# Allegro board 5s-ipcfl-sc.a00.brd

Outline 243.84 x 243.84 mm; copper layers: TOP, VCC, IN1, BOTTOM. Coordinates in mm from the lower left corner of the outline.
Outline path: 0,239.78 arc(1.19,242.65) 4.06,243.84 239.78,243.84 arc(242.65,242.65) 243.84,239.78 243.84,4.06 arc(242.65,1.19) 239.78,0 4.06,0 arc(1.19,1.19) 0,4.06 0,239.78

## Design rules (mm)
net group (8/8): nets CLKOUT_LPC1_CLK_R DRAM_RESET#
net group (+19V): nets +12V +12V_CPU
net group ASM1142_RXN: nets ASM1142_RXN ASM1142_RXN_C
net group ASM1142_RXP: nets ASM1142_RXP ASM1142_RXP_C
net group ASM1142_TXN: nets ASM1142_TXN ASM1142_TXN_C
net group ASM1142_TXP: nets ASM1142_TXP ASM1142_TXP_C
net group CEN_B: nets CEN_B CEN_R
net group CFAN_TACH: nets CFAN_TACH SYSFAN_TACH
net group CLKOUT_LPC0: nets CLKOUT_LPC0 CLKOUT_LPC0_ESPI_CLK
net group CPU_VIDSCLK: nets CPU_VIDSCLK VIDSCLK
net group CPU_VIDSOUT: nets CPU_VIDSOUT VIDSOUT
net group DIFFPAIR127: nets CPU_DDI3_AUXN CPU_DDI3_AUXP
net group DP_TXN0_RD_OUT: nets DP_TXN0_RD_OUT ML_LANE_0N
net group DP_TXN1_RD_OUT: nets DP_TXN1_RD_OUT ML_LANE_1N
net group DP_TXN2_RD_OUT: nets DP_TXN2_RD_OUT ML_LANE_2N
net group DP_TXN3_RD_OUT: nets DP_TXN3_RD_OUT ML_LANE_3N
net group DP_TXP0_RD_OUT: nets DP_TXP0_RD_OUT ML_LANE_0P
net group DP_TXP1_RD_OUT: nets DP_TXP1_RD_OUT ML_LANE_1P
net group DP_TXP2_RD_OUT: nets DP_TXP2_RD_OUT ML_LANE_2P
net group DP_TXP3_RD_OUT: nets DP_TXP3_RD_OUT ML_LANE_3P
net group FRAME#_ESPI: nets FRAME#_ESPI LFRAME#_ESPI_CS0#
net group GPP_A6_SERIRQ: nets GPP_A6_SERIRQ SERIRQ_ESPI
net group H_TRST#: nets H_TRST# PCH_H_TRST#
net group LAD0_ESPI_IO0: nets LAD0_ESPI_IO0 LAD_ESPI0
net group LAD0_ESPI_IO1: nets LAD0_ESPI_IO1 LAD_ESPI1
net group LAD0_ESPI_IO2: nets LAD0_ESPI_IO2 LAD_ESPI2
net group LAD0_ESPI_IO3: nets LAD0_ESPI_IO3 LAD_ESPI3
net group LAN_TXN: nets LAN_TXN LAN_TXN_C
net group LAN_TXP: nets LAN_TXP LAN_TXP_C
net group LFE_B: nets LFE_B LFE_R
net group LGHG(20/20): nets +1VSB_HG_D +1VSB_LG_D
net group LINE1_L: nets LINE1_L LINE1_L_B
net group LINE1_R: nets LINE1_R LINE1_R_B
net group LP1+: nets LP1+ USBP1
net group LP1-: nets LP1- USBN1
net group LP2+: nets LP2+ USBP2
net group LP2-: nets LP2- USBN2
net group LP3+: nets LP3+ USBP3
net group LP3-: nets LP3- USBN3
net group LP4+: nets LP4+ USBP4
net group LP4-: nets LP4- USBN4
net group LP5+: nets LP5+ USBP5
net group LP5-: nets LP5- USBN5
net group LP6+: nets LP6+ USBP6
net group LP6-: nets LP6- USBN6
net group LP7+: nets LP7+ USB2_P2_P_CHARGE
net group LP7-: nets LP7- USB2_P2_N_CHARGE
net group LP9+: nets LP9+ USBP9
net group LP9-: nets LP9- USBN9
net group LP10+: nets LP10+ USBP10
net group LP10-: nets LP10- USBN10
net group LP11+: nets LP11+ USBP11
net group LP11-: nets LP11- USBN11
net group LP12+: nets LP12+ USBP12
net group LP12-: nets LP12- USBN12
net group LP13+: nets LP13+ USB2_P1_P_CHARGE
net group LP13-: nets LP13- USB2_P1_N_CHARGE
net group LP14+: nets LP14+ USBP14
net group LP14-: nets LP14- USBN14
net group MIC1_JD: nets MIC1_JD SENSEA
net group MIC2-L: nets MIC2-L XMIC2_L
net group MIC2-R: nets MIC2-R XMIC2_R
net group PCH_SUSACK#: nets PCH_SUSACK# PCH_SUSWARN#
net group PCH_SUSCLK: nets PCH_SUSCLK SSD_SUSCLK
net group PE5_TXN: nets PE5_TXN PE5_TXN_C
net group PE5_TXN1_C: nets PE5_TXN1_C WLAN_TXN1
net group PE5_TXP: nets PE5_TXP PE5_TXP_C
net group PE5_TXP1_C: nets PE5_TXP1_C WLAN_TXP1
net group PE6_TXN: nets PE6_TXN PE6_TXN_C
net group PE6_TXP: nets PE6_TXP PE6_TXP_C
net group PE7_TXN: nets PE7_TXN PE7_TXN_C
net group PE7_TXP: nets PE7_TXP PE7_TXP_C
net group PE8_TXN: nets PE8_TXN PE8_TXN_C
net group PE8_TXP: nets PE8_TXP PE8_TXP_C
net group PE17_TXN: nets PE17_TXN PE17_TXN1_C
net group PE17_TXP: nets PE17_TXP PE17_TXP1_C
net group PE18_TXN: nets PE18_TXN PE18_TXN2_C
net group PE18_TXP: nets PE18_TXP PE18_TXP2_C
net group PE19_TXN: nets PE19_TXN PE19_TXN3_C
net group PE19_TXP: nets PE19_TXP PE19_TXP3_C
net group PE20_TXN: nets PE20_TXN PE20_TXN4_C
net group PE20_TXP: nets PE20_TXP PE20_TXP4_C
net group PROC_AUDIO_CLK: nets PROC_AUDIO_CLK PROC_AUDIO_CLK_R
net group PROC_AUDIO_SDI: nets PROC_AUDIO_SDI PROC_AUDIO_SDI_R
net group PROC_AUDIO_SDO: nets PROC_AUDIO_SDO PROC_AUDIO_SDO_R
net group PS_ON#: nets P1_PSON# PS_ON#
net group SATA_RXN3: nets SATA_RXN3 SATA_RXN3_C
net group SATA_RXP3: nets SATA_RXP3 SATA_RXP3_C
net group SATA_TXN3: nets SATA_TXN3 SATA_TXN3_C
net group SATA_TXP3: nets SATA_TXP3 SATA_TXP3_C
net group SPI_CS0#: nets SPI_CS0# XSPI_CS#
net group U2DM_A: nets U2DM_A U2DM_A-
net group U2DM_B: nets U2DM_B U2DM_B_C
net group U2DP_A: nets U2DP_A U2DP_A+
net group U2DP_B: nets U2DP_B U2DP_B_C
net group U3RXN_A: nets U3RXN_A U3RXN_A_C
net group U3RXP_A: nets U3RXP_A U3RXP_A_C
net group USB3_RX_N1: nets USB3_RX_N1 USB3_RX_N1_C
net group USB3_RX_N2: nets USB3_RX_N2 USB3_RX_N2_C
net group USB3_RX_N3: nets USB3_RX_N3 USB3_RX_N3_C
net group USB3_RX_N4: nets USB3_RX_N4 USB3_RX_N4_C
net group USB3_RX_N5: nets USB3_RX_N5 USB3_RX_N5_C
net group USB3_RX_N6: nets USB3_RX_N6 USB3_RX_N6_C
net group USB3_RX_N7: nets USB3_RX_N7 USB3_RX_N7_C
net group USB3_RX_P1: nets USB3_RX_P1 USB3_RX_P1_C
net group USB3_RX_P2: nets USB3_RX_P2 USB3_RX_P2_C
net group USB3_RX_P3: nets USB3_RX_P3 USB3_RX_P3_C
net group USB3_RX_P4: nets USB3_RX_P4 USB3_RX_P4_C
net group USB3_RX_P5: nets USB3_RX_P5 USB3_RX_P5_C
net group USB3_RX_P6: nets USB3_RX_P6 USB3_RX_P6_C
net group USB3_RX_P7: nets USB3_RX_P7 USB3_RX_P7_C
net group USB3P1_RXN1: nets USB3P1_RXN1 USB3P1_RXN1_C
net group USB3P1_RXN2: nets USB3P1_RXN2 USB3P1_RXN2_C
net group USB3P1_RXP1: nets USB3P1_RXP1 USB3P1_RXP1_C
net group USB3P1_RXP2: nets USB3P1_RXP2 USB3P1_RXP2_C
net group XTAL: nets LAN_XTAL_IN LAN_Y4_25M
net group XTAL_24M_PCH_IN: nets XTAL_24M_PCH_IN Y18_R
net group 50OHM(4|3.5): nets CLKOUT_LPC1 CPU_VIDALERT# DDPD_HPD MF_MODE# SPI_CS# SPI_DI SPI_IO2 SYS_RESET# U4_SPI_CLK U4_SPI_DO
net group 85OHM(DP_4/4/2.5/200): nets LAN_RXN LAN_RXN_C LAN_RXP LAN_RXP_C PCIE_RCOMPN_W15S15MIL PCIE_RCOMPP_W15S15MIL USBN8 USBP8
net group (5/5): nets AZ_BITCLK AZ_RST# AZ_SDATA_OUT AZ_SYNC CPUPWRGD H_TRIGIN H_TRIGOUT H_TRIGOUT_R HDA_AZRST#_L500MIL HDA_BITCLK_24MHZ_L500MIL HDA_SDO_L500MIL HDA_SYNC_L500MIL N23556498 PCH_TGR_L900MIL PCIE-WAKE_C PM_DOWN PM_DOWN_R PM_SYNC PM_SYNC_R PROCHOT# PROCHOT#_R PROCPWRGD SPI_IO2_XDP SPI_MOSI WAKE#
net group (10): nets SIDE-R_C
net group (10/10): nets +BAT_R +BATT CATERR# CEN_JD CENTER CENTER_C FRONT-L FRONT-L_C FRONT-L_MUTE FRONT-R FRONT-R_C FRONT-R_MUTE FRONT_JD FRONT_L FRONT_L_B FRONT_R FRONT_R_B H_THMTRIP# H_THMTRIP#_R JDREF KBRST#_ESPI LAN_WAKE# LANWAKE_N LFE LFE_C LINE1-L LINE1-L_C LINE1-R LINE1-R_C LINE1_JD LINE2-L LINE2-L_C LINE2-L_MUTE LINE2-R LINE2-R_C LINE2-R_MUTE MIC1-L MIC1-L_C MIC1-R MIC1-R_C MIC1-VREFO-L MIC1-VREFO-R MIC1_L_B MIC1_R_B MIC2-L_C MIC2-R_C MIC2-VREFO MUTE PCH_DPWROK PCH_PWROK PLTRST_CPU# RTCRST# S/PDIF_OUT SENSEB SIDE-L SIDE-L_C SIDE-R SIDE_JD SIDESURR_L SIDESURR_L_B SIDESURR_L_MUTE SIDESURR_R SIDESURR_R_B SIDESURR_R_MUTE SRTCRST# SURR-L SURR-L_C SURR-R SURR-R_C SURR_JD SURR_L SURR_L_B SURR_R SURR_R_B XLINE2_L XLINE2_R XMIC2_L_D XMIC2_R_D
net group (15/15): nets EXP_TXN0 EXP_TXN1 EXP_TXN2 EXP_TXN3 EXP_TXN4 EXP_TXN5 EXP_TXN6 EXP_TXN7 EXP_TXP0 EXP_TXP1 EXP_TXP2 EXP_TXP3 EXP_TXP4 EXP_TXP5 EXP_TXP6 EXP_TXP7 PE9_TXN PE9_TXP PE10_TXN PE10_TXP PE11_TXN PE11_TXP PE12_TXN PE12_TXP PECI_PCH PECI_SIO SATA_RXN0 SATA_RXN1 SATA_RXN2 SATA_RXP0 SATA_RXP1 SATA_RXP2 SATA_TXN0 SATA_TXN1 SATA_TXN2 SATA_TXP0 SATA_TXP1 SATA_TXP2 SPI_CLK XSPI_CLK
net group (20/20): nets CK_100M_ASM1142 CK_100M_ASM1142# N23059953 RTCX1_NO_IO_HS_S20MIL XCLK_BIASREF_WSL
net group (25/25): nets RBIAS
net group (PWR_10): nets 3VA_ADJ_A 3VA_ADJ_C_A +1VSB_DUAL_IN_CRT_MAIN +1VSB_DUAL_IN_CRT_MAIN_R +1VSB_DUAL_IN_CRT_SB_R +1VSB_FB_A +1VSB_FB_RC_A +1VSB_TST_A +1VSB_VCC_A +CPUIO_FB_A +CPUIO_FBR_A CC1 CC2 SLP_SUS#_CRT_R VCC_SENSE VCCGT_SENSE VCCIO_SENSE VCCSA_SENSE VGT_COMP_A VGT_FB_A VGT_IMON_A VRM_EN_A VSS_SENSE VSSGT_SENSE
net group (PWR_15): nets +V1P0A_VCCF24_W15MIL CC_VCONN CC_VCONN_EN
net group (PWR_20): nets +0P95V_CPUIO +1P2V +1P2V_DUAL +1P2V_FB +1P2V_FB_R +1P2V_SUS +1P2V_VDD +1P05V_SA +1V_DCPDSW +1V_ST +1VSB +1VSB_BOT_C +1VSB_BOTR_C +1VSB_SN +1VSB_TRIP +1VSB_VIN +2P5V_VPP +3.3V_SUS +3P3V +3P3V_DP +3P3VA +3P3VSB +5V +5V_1VSB_IN +5V_DUAL +5VA +5VSB +12V_GFX +CPUIO_RC1 +CPUIO_RC2 +CPUIO_SS +USB_TYPEC +VCCGT +VCORE +VTT_DDR AGND BAT GND VGT_PWM1_SN VGT_PWM2_BOT_C VGT_PWM2_BOTR_C VGT_PWM2_SN VGT_PWM2_VCC_C VRM_PWM1_SN VRM_PWM2_SN VRM_PWM3_BOT_C VRM_PWM3_BOTR_C VRM_PWM3_SN VRM_PWM3_VCC_C VRM_PWM4_BOT_C VRM_PWM4_BOTR_C VRM_PWM4_SN VRM_PWM4_VCC_C
net group (PWR_25): nets +1VSB_HGR_D +1VSB_SW_C +CPUIO_DRV_D +CPUIO_DRVR_D +V1P0A_VCCAMPHYPLL_W25MIL VGT_PWM1_HGR_D VGT_PWM2_HG_D VGT_PWM2_HGR_D VGT_PWM2_LG_D VGT_PWM2_SW_C VRM_PWM1_HGR_D VRM_PWM2_HGR_D VRM_PWM3_HG_D VRM_PWM3_HGR_D VRM_PWM3_LG_D VRM_PWM3_SW_C VRM_PWM4_HG_D VRM_PWM4_HGR_D VRM_PWM4_LG_D VRM_PWM4_SW_C
net group (PWR_40): nets +5V_LDO
net group AUDIO: nets CEN_MUTE LFE_MUTE LINE2_JD MIC1_L MIC1_R MIC2_JD SURR-L_MUTE SURR-R_MUTE
net group AZALIA: nets AZ_SDATA_IN0
net group COMP: nets H_CFG_RCOMP
net group CPU_VIDALERT#: nets VIDALERT#
net group EXP1_TXN8_C: nets EXP_TXN8
net group EXP1_TXN9_C: nets EXP_TXN9
net group EXP1_TXN10_C: nets EXP_TXN10
net group EXP1_TXN11_C: nets EXP_TXN11
net group EXP1_TXN12_C: nets EXP_TXN12
net group EXP1_TXN13_C: nets EXP_TXN13
net group EXP1_TXN14_C: nets EXP_TXN14
net group EXP1_TXN15_C: nets EXP_TXN15
net group EXP1_TXP8_C: nets EXP_TXP8
net group EXP1_TXP9_C: nets EXP_TXP9
net group EXP1_TXP10_C: nets EXP_TXP10
net group EXP1_TXP11_C: nets EXP_TXP11
net group EXP1_TXP12_C: nets EXP_TXP12
net group EXP1_TXP13_C: nets EXP_TXP13
net group EXP1_TXP14_C: nets EXP_TXP14
net group EXP1_TXP15_C: nets EXP_TXP15
net group H_PRDY#: nets H_PRDY# PCHXDP_PRDY# XDP2_OBSFN_A1
net group HDMI_DDC: nets DONGLE_CTRL_AUX_DN DONGLE_CTRL_AUX_DP DP_AUXN_DP_OUT DP_AUXP_DP_OUT
net group M_MIS: nets CPU_VREF_CA_A CPU_VREF_CA_B DDR_VREF_CA_B_R
net group OTHER: nets HD_LED#
net group PE9_TXN: nets PE9_TXN_C
net group PE9_TXP: nets PE9_TXP_C
net group PE10_TXN: nets PE10_TXN_C
net group PE10_TXP: nets PE10_TXP_C
net group PE11_TXN: nets PE11_TXN_C
net group PE11_TXP: nets PE11_TXP_C
net group PE12_TXN: nets PE12_TXN_C
net group PE12_TXP: nets PE12_TXP_C
net group REM: nets REMOTE1+ REMOTE1- REMOTE2+ REMOTE2-
net group SATA_RXN0: nets SATA_RXN0_C
net group SATA_RXN1: nets SATA_RXN1_C
net group SATA_RXN2: nets SATA_RXN2_C
net group SATA_RXP0: nets SATA_RXP0_C
net group SATA_RXP1: nets SATA_RXP1_C
net group SATA_RXP2: nets SATA_RXP2_C
net group SATA_TXN0: nets SATA_TXN0_C
net group SATA_TXN1: nets SATA_TXN1_C
net group SATA_TXN2: nets SATA_TXN2_C
net group SATA_TXP0: nets SATA_TXP0_C
net group SATA_TXP1: nets SATA_TXP1_C
net group SATA_TXP2: nets SATA_TXP2_C
net group SMB(4/10): nets SMB_CLK_RESUME_DAC SMB_CLK_RESUME_WLAN SMB_DATA_RESUME_DAC SMB_DATA_RESUME_WLAN SML1_CLK_SIO SML1_DATA_SIO
net group SMBUS: nets SMB_CLK_MAIN SMB_CLK_RESUME SMB_DATA_MAIN SMB_DATA_RESUME
net group SPI: nets SPI_IO3 SPI_MISO SPI_MOSI_XDP
net group SVID: nets VRM_ALERT#
net group U3TXN_A: nets U3TXN_A U3TXN_A_CMC U3TXN_AMC
net group U3TXP_A: nets U3TXP_A U3TXP_A_CMC U3TXP_AMC
net group USB3.0(15/15): nets U3RXN_B U3RXP_B U3TXN_B U3TXP_B
net group USB3_SS_TXN1_C: nets USB3_SS_TXN1_C USB3_SS_TXN1_CMC USB3_TX_N1
net group USB3_SS_TXN2_C: nets USB3_SS_TXN2_C USB3_SS_TXN2_CMC USB3_TX_N2
net group USB3_SS_TXN3_C: nets USB3_SS_TXN3_C USB3_SS_TXN3_CMC USB3_TX_N3
net group USB3_SS_TXN4_C: nets USB3_SS_TXN4_C USB3_SS_TXN4_CMC USB3_TX_N4
net group USB3_SS_TXP1_C: nets USB3_SS_TXP1_C USB3_SS_TXP1_CMC USB3_TX_P1
net group USB3_SS_TXP2_C: nets USB3_SS_TXP2_C USB3_SS_TXP2_CMC USB3_TX_P2
net group USB3_SS_TXP3_C: nets USB3_SS_TXP3_C USB3_SS_TXP3_CMC USB3_TX_P3
net group USB3_SS_TXP4_C: nets USB3_SS_TXP4_C USB3_SS_TXP4_CMC USB3_TX_P4
net group USB3_TX_N5: nets USB3_TX_N5 USB3_TX_N5_C USB3_TX_N5_CMC
net group USB3_TX_N6: nets USB3_TX_N6 USB3_TX_N6_C USB3_TX_N6_CMC
net group USB3_TX_N7: nets USB3_TX_N7 USB3_TX_N7_C USB3_TX_N7_CMC
net group USB3_TX_P5: nets USB3_TX_P5 USB3_TX_P5_C USB3_TX_P5_CMC
net group USB3_TX_P6: nets USB3_TX_P6 USB3_TX_P6_C USB3_TX_P6_CMC
net group USB3_TX_P7: nets USB3_TX_P7 USB3_TX_P7_C USB3_TX_P7_CMC
net group USB3P1_TXN1: nets USB3P1_TXN1 USB3P1_TXN2_CMC USB3P1_TXN2_R
net group USB3P1_TXN1_CMC: nets USB3P1_TXN1_CMC USB3P1_TXN1_R USB3P1_TXN2
net group USB3P1_TXP1: nets USB3P1_TXP1 USB3P1_TXP2_CMC USB3P1_TXP2_R
net group USB3P1_TXP1_CMC: nets USB3P1_TXP1_CMC USB3P1_TXP1_R USB3P1_TXP2

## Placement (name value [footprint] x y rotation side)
AC1  0.1UF/6.3V  [MX_C0201]  22.73 19.35 180 top
AC2  0.1UF/6.3V  [MX_C0201]  22.73 20.27 180 top
AC3  10UF/6.3V  [MX_C0603_SMALL_T01]  6.88 14.86 180 top
AC4  0.1UF/6.3V  [MX_C0201]  9.53 14.73 270 top
AC14  0.1UF/6.3V  [MX_C0201]  23.06 17.4 90 top
AC15  10UF/6.3V  [MX_C0603_SMALL_T01]  25.07 17.45 90 top
AC16  10UF/6.3V  [MX_C0603_SMALL_T01]  7.62 17.66 180 top
AC17  0.1UF/6.3V  [MX_C0201]  13.72 8.38 270 top
AC18  10UF/6.3V  [MX_C0603_SMALL_T01]  11.81 8.51 180 top
AC19  0.1UF/6.3V  [MX_C0201]  9.02 18.92 180 top
AC20  10UF/6.3V  [MX_C0603_SMALL_T01]  26.64 13.74 0 top
AC21  0.1UF/6.3V  [MX_C0201]  22.23 12.06 270 top
AC22  22PF/50V  [MX_C0402_SMALL_T01]  23.62 14.86 0 top
AC23  10UF/6.3V  [MX_C0603_SMALL_T01]  7.62 16.26 180 top
AC24  100PF/50V  [MX_C0402_SMALL_T01]  29.72 11.3 90 top
AC25  0.1UF/16V  [MX_C0402_SMALL_T01]  31.37 11.3 90 top
AC26  100PF/50V  [MX_C0402_SMALL_T01]  18.16 70.99 0 top
AC27  0.1UF/16V  [MX_C0402_SMALL_T01]  19.43 34.8 0 top
AC39  0.1UF/16V  [MX_C0402_SMALL_T01]  216.08 22.05 270 top
AC47  10PF/50V  [MX_C0402_SMALL_T01]  204.22 35.31 180 top
AC52  100PF/50V  [MX_C0402_SMALL_T01]  18.16 75.06 0 top
AC55  100PF/50V  [MX_C0402_SMALL_T01]  18.16 58.04 0 top
AC71  22UF/6.3V  [MX_C0603_SMALL_T02]  30.23 27 270 top
AC72  100PF/50V  [MX_C0402_SMALL_T01]  41.17 5.46 180 top
AC73  100PF/50V  [MX_C0402_SMALL_T01]  20.57 11.18 45 top
AC74  100PF/50V  [MX_C0402_SMALL_T01]  27.23 7.75 180 top
AC75  100PF/50V  [MX_C0402_SMALL_T01]  30.86 7.75 0 top
AC76  100PF/50V  [MX_C0402_SMALL_T01]  34.54 7.75 180 top
AC77  100PF/50V  [MX_C0402_SMALL_T01]  37.97 7.75 180 top
AC129  0.1UF/16V  [MX_C0402_SMALL_T01]  40.13 8.38 0 top
AC130  0.1UF/16V  [MX_C0402_SMALL_T01]  18.67 82.68 0 top
AC136  1UF/6.3V  [MX_C0402_SMALL_T01]  13.94 175.44 270 top
AC161  10UF/16V  [C1206_H75]  15.11 24.13 270 top
AC162  10UF/16V  [C1206_H75]  17.65 24.13 270 top
AC163  10UF/16V  [C1206_H75]  12.45 24.13 270 top
AC164  10UF/16V  [C1206_H75]  9.91 24.13 270 top
AC165  10UF/25V  [CE_59_BD177_H236_HD28_LF5]  6.15 26.92 270 top
AC166  10UF/25V  [CE_59_BD177_H236_HD28_LF5]  6.15 21.77 270 top
AC167  10UF/25V  [CE_59_BD177_H236_HD28_LF5]  7.75 54.48 270 top
AC168  10UF/25V  [CE_59_BD177_H236_HD28_LF5]  12.95 54.48 270 top
AC169  10UF/25V  [CE_59_BD177_H236_HD28_LF5]  7.24 45.21 270 top
AC170  10UF/25V  [CE_59_BD177_H236_HD28_LF5]  12.45 45.21 270 top
AC171  10UF/25V  [CE_59_BD177_H236_HD28_LF5]  4.83 49.83 270 top
AC172  10UF/25V  [CE_59_BD177_H236_HD28_LF5]  10.03 49.83 270 top
AC173  100PF/50V  [MX_C0402_SMALL_T01]  7.57 68.58 180 top
AC174  100PF/50V  [MX_C0402_SMALL_T01]  5.26 68.58 180 top
AC175  100PF/50V  [MX_C0402_SMALL_T01]  9.88 68.58 180 top
AC176  100PF/50V  [MX_C0402_SMALL_T01]  12.19 68.58 180 top
AC177  100PF/50V  [MX_C0402_SMALL_T01]  16.81 68.58 180 top
AC178  100PF/50V  [MX_C0402_SMALL_T01]  14.5 68.58 180 top
AC179  100PF/50V  [MX_C0402_SMALL_T01]  17.32 89 180 top
AC180  100PF/50V  [MX_C0402_SMALL_T01]  19.56 88.95 180 top
AC181  100PF/50V  [MX_C0402_SMALL_T01]  11.94 88.14 180 top
AC182  100PF/50V  [MX_C0402_SMALL_T01]  10.11 89.66 90 top
AC183  100PF/50V  [MX_C0402_SMALL_T01]  6.64 88.27 270 top
AC184  100PF/50V  [MX_C0402_SMALL_T01]  5.46 71.88 270 top
AC185  100PF/50V  [MX_C0402_SMALL_T01]  14.61 222.38 180 top
AC186  0.015U/16V  [MX_C0402_SMALL_T01]  16 226.57 270 top
AC187  0.1UF/6.3V  [MX_C0201]  14.1 226.57 90 top
AC188  10UF/6.3V  [MX_C0603_SMALL_T01]  23.88 13.71 0 top
AC193  100PF/50V  [MX_C0402_SMALL_T01]  59.45 8.78 180 top
AC194  100PF/50V  [MX_C0402_SMALL_T01]  72.12 9.27 90 top
AC195  100PF/50V  [MX_C0402_SMALL_T01]  74.86 9.27 90 top
AC196  100PF/50V  [MX_C0402_SMALL_T01]  78.12 9.71 0 top
AC197  100PF/50V  [MX_C0402_SMALL_T01]  59.87 11.51 0 top
AC198  0.1UF/16V  [MX_C0402_SMALL_T01]  28.7 29.92 0 top
ACE3  100uF/16V  [MX_CE_100U_16V_6D3X7_LFH]  17.81 4.75 0 top
ACE4  330UF/6.3V  [MX_CE_330U_6D3V_6D3X11_LFH]  18.54 44.7 270 top
ACE5  10UF/25V  [CE_59_BD177_H236_HD28_LF5]  6.48 5.08 270 top
ACE6  10UF/25V  [CE_59_BD177_H236_HD28_LF5]  11.68 5.08 270 top
ACE7  330UF/6.3V  [MX_CE_330U_6D3V_6D3X11_LFH]  18.54 51.82 270 top
AD1  BAT54A_NL  [MX_SOT23_2D4_H43]  23.44 5.64 90 top
AD2  AZ5125-01J  [MX_S0402_AMAZ_COLAY]  20.32 32.26 90 top
AD3  CDS2C05GTA  [MX_VARISTOR_0402]  19.43 89.94 180 top
AD4  CDS2C05GTA  [MX_VARISTOR_0402]  12.19 89.53 90 top
AD5  CDS2C05GTA  [MX_VARISTOR_0402]  11.1 89.53 270 top
AD6  CDS2C05GTA  [MX_VARISTOR_0402]  6.73 89.79 180 top
AD7  CDS2C05GTA  [MX_VARISTOR_0402]  4.45 71.88 270 top
AD8  CDS2C05GTA  [MX_VARISTOR_0402]  41.02 4.45 0 top
AD9  CDS2C05GTA  [MX_VARISTOR_0402]  25.76 10.92 90 top
AD10  CDS2C05GTA  [MX_VARISTOR_0402]  28.7 11.3 90 top
AD11  CDS2C05GTA  [MX_VARISTOR_0402]  32.89 11.3 90 top
AD12  CDS2C05GTA  [MX_VARISTOR_0402]  36.96 10.92 90 top
AD13  CDS2C05GTA  [MX_VARISTOR_0402]  7.42 69.6 180 top
AD14  CDS2C05GTA  [MX_VARISTOR_0402]  5.26 69.6 180 top
AD15  CDS2C05GTA  [MX_VARISTOR_0402]  9.88 69.6 180 top
AD16  CDS2C05GTA  [MX_VARISTOR_0402]  12.57 69.6 180 top
AD17  CDS2C05GTA  [MX_VARISTOR_0402]  16.81 69.6 180 top
AD18  CDS2C05GTA  [MX_VARISTOR_0402]  14.5 69.6 180 top
AD19  CDS2C05GTA  [MX_VARISTOR_0402]  17.48 89.97 180 top
AD20  CDS2C05GTA  [MX_VARISTOR_0402]  61.23 10.45 90 top
AD21  CDS2C05GTA  [MX_VARISTOR_0402]  71.16 9.3 90 top
AD22  CDS2C05GTA  [MX_VARISTOR_0402]  75.83 9.3 90 top
AD23  CDS2C05GTA  [MX_VARISTOR_0402]  67.67 9.02 180 top
AL1  30Ohm/100Mhz  [MX_L0603_SMALL_T02]  19.43 30.48 180 top
AL2  30Ohm/100Mhz  [MX_L0603_SMALL_T02]  26.42 17.45 270 top
AL3  30Ohm/100Mhz  [MX_L0603_SMALL_T02]  14.5 67.44 0 top
AL4  30Ohm/100Mhz  [MX_L0603_SMALL_T02]  17.4 87.88 180 top
AL5  30Ohm/100Mhz  [MX_L0603_SMALL_T02]  16.81 67.44 0 top
AL6  30Ohm/100Mhz  [MX_L0603_SMALL_T02]  19.56 87.38 270 top
AL7  30Ohm/100Mhz  [MX_L0603_SMALL_T02]  12.19 67.44 0 top
AL8  30Ohm/100Mhz  [MX_L0603_SMALL_T02]  13.97 88.49 0 top
AL9  30Ohm/100Mhz  [MX_L0603_SMALL_T02]  9.88 67.44 0 top
AL10  30Ohm/100Mhz  [MX_L0603_SMALL_T02]  9.45 88.19 180 top
AL11  30Ohm/100Mhz  [MX_L0603_SMALL_T02]  5.26 67.44 0 top
AL12  30Ohm/100Mhz  [MX_L0603_SMALL_T02]  5.08 88.49 180 top
AL13  30Ohm/100Mhz  [MX_L0603_SMALL_T02]  7.57 67.44 0 top
AL14  30Ohm/100Mhz  [MX_L0603_SMALL_T02]  6.6 71.75 270 top
AL15  30Ohm/100Mhz  [MX_L0603_SMALL_T02]  38.23 9.4 270 top
AL16  30Ohm/100Mhz  [MX_L0603_SMALL_T02]  34.29 8.89 0 top
AL17  30Ohm/100Mhz  [MX_L0603_SMALL_T02]  29.9 9.14 0 top
AL18  30Ohm/100Mhz  [MX_L0603_SMALL_T02]  25.27 8.08 0 top
AMB_Q1  PMBS3904  [MX_SOT23]  227.69 76.89 180 top
APR13  0  [MX_R0402_SMALL_T01]  213.28 8.26 270 top
APR112  10K  [MX_R0402_SMALL_T01]  25.32 143.59 180 top
AQ1  HBN2444S6R  [MX_SOT363_PHILIPS]  15.62 62.87 90 top
AQ2  HBN2444S6R  [MX_SOT363_PHILIPS]  10.92 62.87 270 top
AQ11  PMBS3906  [MX_SOT23]  22.82 25.15 270 top
AQ13  PMBS3906  [MX_SOT23]  26.02 25.15 270 top
AQ14  PMBS3906  [MX_SOT23]  25.53 29.03 0 top
AQ16  HBN2444S6R  [MX_SOT363_PHILIPS]  6.22 62.87 90 top
AQ17  HBN2444S6R  [MX_SOT363_PHILIPS]  5.97 58.42 90 top
AQ18  HBN2444S6R  [MX_SOT363_PHILIPS]  13.11 58.48 90 top
AQ23  PMBS3906  [MX_SOT23]  29.46 15.29 270 top
AR1  1K  [MX_R0402_SMALL_T01]  27.43 22.48 0 top
AR2  22  [MX_R0402_SMALL_T01]  23.62 16 180 top
AR3  47K  [MX_R0402_SMALL_T01]  24.89 20.45 180 top
AR4  4.7K  [MX_R0402_SMALL_T01]  22.73 21.21 180 top
AR5  75  [MX_R0402_SMALL_T01]  36.32 9.53 0 top
AR6  75  [MX_R0402_SMALL_T01]  32.13 8.26 90 top
AR7  7.5  [MX_R0402_SMALL_T01]  23.29 8.56 0 top
AR8  7.5  [MX_R0402_SMALL_T01]  27.41 9.27 90 top
AR9  22K  [MX_R0402_SMALL_T01]  28.32 9.27 270 top
AR10  22K  [MX_R0402_SMALL_T01]  23.29 9.47 180 top
AR11  20K  [MX_R0402_SMALL_T01]  8.61 12.83 270 top
AR12  4.7K  [MX_R0402_SMALL_T01]  31.88 9.53 0 top
AR13  4.7K  [MX_R0402_SMALL_T01]  36.32 8.61 0 top
AR14  5.1K  [MX_R0402_SMALL_T01]  18.59 27.48 180 top
AR15  10K  [MX_R0402_SMALL_T01]  18.59 28.37 180 top
AR16  20K  [MX_R0402_SMALL_T01]  18.59 26.62 180 top
AR17  39.2K  [MX_R0402_SMALL_T01]  19.56 25.27 90 top
AR18  5.1K  [MX_R0402_SMALL_T01]  6.78 12.83 270 top
AR19  10K  [MX_R0402_SMALL_T01]  9.53 12.83 270 top
AR20  0  [MX_R0402_SMALL_T01]  14.69 227.94 180 top
AR23  0  [MX_R0402_SMALL_T01]  20.57 27.81 0 top
AR25  39.2K  [MX_R0402_SMALL_T01]  7.7 12.83 270 top
AR26  20K  [MX_R0402_SMALL_T01]  14.73 8.38 270 top
AR50  1K  [MX_R0402_SMALL_T01]  21.34 22.17 90 top
AR53  10K  [MX_R0402_SMALL_T01]  24.38 22.48 180 top
AR55  10K  [MX_R0402_SMALL_T01]  28.57 26.72 180 top
AR56  200K  [MX_R0402_SMALL_T01]  28.57 27.64 0 top
AR57  0  [MX_R0603_SMALL_T01]  28.96 28.78 0 top
AR61  1K  [MX_R0402_SMALL_T01]  16 60.71 90 top
AR62  1K  [MX_R0402_SMALL_T01]  15.09 60.71 90 top
AR63  1K  [MX_R0402_SMALL_T01]  10.39 60.71 90 top
AR64  1K  [MX_R0402_SMALL_T01]  11.3 60.71 90 top
AR199  1K  [MX_R0402_SMALL_T01]  5.66 60.71 270 top
AR200  1K  [MX_R0402_SMALL_T01]  4.74 60.71 270 top
AR201  1K  [MX_R0402_SMALL_T01]  7.49 60.71 90 top
AR202  1K  [MX_R0402_SMALL_T01]  6.58 60.71 90 top
AR203  1K  [MX_R0402_SMALL_T01]  13.59 60.71 90 top
AR204  1K  [MX_R0402_SMALL_T01]  12.67 60.71 270 top
AR205  22K  [MX_R0402_SMALL_T01]  14.3 66.29 0 top
AR206  22K  [MX_R0402_SMALL_T01]  16.5 66.29 0 top
AR207  75  [MX_R0402_SMALL_T01]  14.3 65.28 180 top
AR208  75  [MX_R0402_SMALL_T01]  16.5 65.28 180 top
AR209  75  [MX_R0402_SMALL_T01]  17.4 86.74 0 top
AR210  75  [MX_R0402_SMALL_T01]  17.91 85.47 180 top
AR211  75  [MX_R0402_SMALL_T01]  12.14 65.28 180 top
AR212  75  [MX_R0402_SMALL_T01]  15.49 86.97 270 top
AR213  75  [MX_R0402_SMALL_T01]  9.88 65.28 180 top
AR214  75  [MX_R0402_SMALL_T01]  7.84 88.39 90 top
AR215  75  [MX_R0402_SMALL_T01]  5.26 65.28 180 top
AR216  1K  [MX_R0402_SMALL_T01]  4.83 86.46 0 top
AR217  75  [MX_R0402_SMALL_T01]  7.57 65.28 180 top
AR218  1K  [MX_R0402_SMALL_T01]  8.37 70.94 0 top
AR219  2.2K  [MX_R0402_SMALL_T01]  4.83 87.38 0 top
AR220  22K  [MX_R0402_SMALL_T01]  7.57 66.29 0 top
AR221  22K  [MX_R0402_SMALL_T01]  5.26 66.29 0 top
AR222  22K  [MX_R0402_SMALL_T01]  9.88 66.29 0 top
AR223  2.2K  [MX_R0402_SMALL_T01]  8.37 71.86 0 top
AR224  22K  [MX_R0402_SMALL_T01]  12.09 66.29 0 top
AR225  22K  [MX_R0402_SMALL_T01]  8.89 89.66 90 top
AR226  22K  [MX_R0402_SMALL_T01]  14.22 87.35 180 top
AR227  220  [MX_R0402_SMALL_T01]  14.61 223.47 180 top
AR228  100 Ohm  [MX_R0402_SMALL_T01]  14.61 224.49 180 top
AR229  8.2K  [MX_R0402_SMALL_T01]  42.16 6.38 180 top
AR231  0  [MX_R0402_SMALL_T01]  33.91 11.3 90 top
AR232  0  [MX_R0402_SMALL_T01]  18.16 76.58 0 top
AR233  0  [MX_R0603_SHORT_SMALL_T01]  215.9 130.56 180 top
AR235  0  [MX_R0603_SHORT_SMALL_T01]  236.85 212.7 180 top
AR237  10K  [MX_R0402_SMALL_T01]  22.99 146.56 180 top
AR238  10K  [MX_R0402_SMALL_T01]  22.76 150.16 180 top
AR241  2.2K  [MX_R0402_SMALL_T01]  15.37 152.65 90 top
AR242  2.2K  [MX_R0402_SMALL_T01]  25.32 144.5 0 top
AR243  2.2K  [MX_R0402_SMALL_T01]  19.56 144.42 180 top
AR244  4.7K  [MX_R0402_SMALL_T01]  33.02 161.16 90 top
AR247  12.1K  [MX_R0402_SMALL_T01]  23.27 152.15 180 top
AR263  1K  [MX_R0402_SMALL_T01]  24.59 10.92 90 top
ASR7  0  [MX_R0402_SMALL_T01]  36.5 150.16 270 top
AU1  ALC3861-CG  [MX_QFP_48P_20_354X354_H63]  16 15.57 90 top
BKPT1  BACKPLANE_7P  [MX_BACKPLANE_7P_S3465_AMCO]  125.45 160.84 90 bottom
BUMPER1  RUBBER_FOOT  [MX_RUBBER_FOOT_C394_NOPAD]  220.27 153.39 180 bottom
BUMPER2  RUBBER_FOOT  [MX_RUBBER_FOOT_C394_NOPAD]  100.61 51.38 180 bottom
BUMPER3  RUBBER_FOOT  [MX_RUBBER_FOOT_C394_NOPAD]  65.86 11.44 180 bottom
BUMPER4  RUBBER_FOOT  [MX_RUBBER_FOOT_C394_NOPAD]  229.86 10.44 180 bottom
C1  150PF/50V  [MX_C0402_SMALL_T01]  215.54 45.09 0 top
C2  150PF/50V  [MX_C0402_SMALL_T01]  213.92 45.09 180 top
C5  0.1UF/16V  [MX_C0402_SMALL_T01]  106.35 10.46 180 top
C81  180PF/50V  [MX_C0402_SMALL_T01]  204.22 28.7 180 top
C82  180PF/50V  [MX_C0402_SMALL_T01]  221.5 43.29 90 top
C83  47PF/50V  [MX_C0402_SMALL_T01]  225.91 26.2 0 top
C85  4.7UF/6.3V  [MX_C0603_SMALL_T01]  204.95 23.01 180 top
C93  0.1UF/6.3V  [MX_C0201]  137.82 15.15 0 top
C414  47PF/50V  [MX_C0402_SMALL_T01]  169.01 24.94 90 top
C415  47PF/50V  [MX_C0402_SMALL_T01]  170.13 24.94 90 top
C416  47PF/50V  [MX_C0402_SMALL_T01]  168.45 29.84 90 top
C417  47PF/50V  [MX_C0402_SMALL_T01]  162.33 31.47 90 top
C9357  0.1UF/6.3V  [MX_C0201]  223.42 102.64 90 top
C941399  0.1UF/6.3V  [MX_C0201]  221.56 116.84 90 top
C941400  0.1UF/6.3V  [MX_C0201]  229.67 104.06 90 top
C941401  0.1UF/6.3V  [MX_C0201]  230.3 115.77 0 top
C941402  0.1UF/16V  [MX_C0402_SMALL_T01]  223.19 99.26 0 top
CB2  1000PF/50V  [MX_C0402_SMALL_T01]  27.84 43.03 0 top
CB4107  0.1UF/6.3V  [MX_C0201]  15.7 139.55 180 top
CB4112  0.1UF/6.3V  [MX_C0201]  16.21 143 90 top
CB4113  0.1UF/6.3V  [MX_C0201]  18.52 142.6 90 top
CB4114  0.1UF/6.3V  [MX_C0201]  15.7 138.63 180 top
CB4115  0.1UF/6.3V  [MX_C0201]  22.96 226.95 270 top
CB4116  0.1UF/6.3V  [MX_C0201]  18.44 227.79 90 top
CB4117  0.1UF/6.3V  [MX_C0201]  14.86 216.41 90 top
CB4119  0.1UF/16V  [MX_C0402_SMALL_T01]  42.42 206.5 90 top
CB4122  1UF/6.3V  [MX_C0402_SMALL_T01]  228.14 137.29 0 top
CB4123  0.1UF/6.3V  [MX_C0201]  225.25 137.31 180 top
CB4124  0.1UF/6.3V  [MX_C0201]  233.86 116 270 top
CB4125  0.1UF/6.3V  [MX_C0201]  43.33 206.5 90 top
CB4126  0.1UF/6.3V  [MX_C0201]  38.48 162.94 270 top
CB4127  0.1UF/6.3V  [MX_C0201]  23.98 143.33 270 top
CB4128  10PF/50V  [MX_C0402_SMALL_T01]  22.91 143.61 270 top
CB4129  10PF/50V  [MX_C0402_SMALL_T01]  21.06 152.27 90 top
CLIP3  ANCHOR  [MX_ANCHOR_2P_100_AMCO_LF3]  195.7 32.38 180 top
CLIP4  ANCHOR  [MX_ANCHOR_2P_100_AMCO_LF3]  145.93 68.96 180 top
CON4  POWER_CON_2X12P  [MX_PWR_2X12P_165_2HD_LF3]  235.81 175.13 90 top
CON_CBAT  BATT_HOLDER  [MX_BATHOLDER_2P_787_LF3]  155.52 101.75 180 top
CON_XMM1  DDR4_DIMM_288P  [MX_DDR4_DIMM_288P_3H_CO]  186.45 161.35 270 top
CON_XMM2  DDR4_DIMM_288P  [MX_DDR4_DIMM_288P_3H_CO]  202.86 161.35 270 top
CON_XMM3  DDR4_DIMM_288P  [MX_DDR4_DIMM_288P_3H_CO]  178.68 161.35 270 top
CON_XMM4  DDR4_DIMM_288P  [MX_DDR4_DIMM_288P_3H_CO]  195.08 161.35 270 top
CR2  GREEN  [MX_LED_2P_63X31_H16]  95.15 8.36 270 top
CR7  GREEN  [MX_LED_2P_63X31_H16]  101.32 8.36 270 top
CR9  RED  [MX_LED_2P_63X31_EVER]  102.9 8.36 270 top
CR15  WHITE  [MX_LED_D_2P_157X327_LF3]  6.35 238 270 top
CR17  0  [MX_R0402_SHORT_SMALL_T01]  35.81 200.66 90 top
CR19  10K  [MX_R0402_SMALL_T01]  38.56 201.55 270 top
CR25  GREEN  [MX_LED_2P_63X31_H16]  99.85 8.36 270 top
CR26  GREEN  [MX_LED_2P_63X31_H16]  98.32 8.36 270 top
CR27  GREEN  [MX_LED_2P_63X31_H16]  96.7 8.36 270 top
D4C1  0.1UF/16V  [MX_C0402_SMALL_T01]  207.28 183.42 0 top
D4C2  0.1UF/6.3V  [MX_C0201]  174.62 106.55 90 top
D4C3  0.1UF/6.3V  [MX_C0201]  173.48 229.87 270 top
D4C4  0.1UF/16V  [MX_C0402_SMALL_T01]  172.85 103.25 270 top
D4C5  0.1UF/16V  [MX_C0402_SMALL_T01]  172.85 104.9 90 top
D4C7  0.1UF/6.3V  [MX_C0201]  190.63 106.68 270 top
D4C8  0.1UF/6.3V  [MX_C0201]  190.63 230.63 90 top
D4C12  0.1UF/6.3V  [MX_C0201]  206.88 107.57 270 top
D4C13  0.1UF/6.3V  [MX_C0201]  206.88 230 90 top
D4C17  0.1UF/6.3V  [MX_C0201]  207.8 107.57 270 top
D4C18  0.1UF/6.3V  [MX_C0201]  208.15 229.62 0 top
D4C21  2.2UF/6.3V  [MX_C0603_SMALL_T01]  190.63 228.57 270 top
D4C22  2.2UF/6.3V  [MX_C0603_SMALL_T01]  172.34 229.36 270 top
D4C23  2.2UF/6.3V  [MX_C0603_SMALL_T01]  207.14 227.97 270 top
D4C24  2.2UF/6.3V  [MX_C0603_SMALL_T01]  208.41 227.97 270 top
D4CB1  4.7UF/10V  [MX_C0603_SMALL_T01]  173.48 164.59 270 top
D4CB2  0.1UF/6.3V  [MX_C0201]  174.55 164.85 270 top
D4CB3  0.1UF/6.3V  [MX_C0201]  172.44 101.27 270 top
D4CB4  0.1UF/6.3V  [MX_C0201]  173.56 101.27 270 top
D4CB5  4.7UF/10V  [MX_C0603_SMALL_T01]  209.85 156.84 0 top
D4CB6  0.1UF/6.3V  [MX_C0201]  207.67 156.97 180 top
D4CB7  0.1UF/6.3V  [MX_C0201]  190.78 103.38 270 top
D4CB8  0.1UF/6.3V  [MX_C0201]  190.75 101.22 270 top
D4CB9  4.7UF/10V  [MX_C0603_SMALL_T01]  207.57 154.56 180 top
D4CB10  0.1UF/6.3V  [MX_C0201]  190.83 165.99 90 top
D4CB11  0.1UF/6.3V  [MX_C0201]  207.8 105.79 90 top
D4CB12  0.1UF/6.3V  [MX_C0201]  206.88 105.79 90 top
D4CB13  4.7UF/10V  [MX_C0603_SMALL_T01]  207.57 155.8 180 top
D4CB14  0.1UF/6.3V  [MX_C0201]  206.91 164.59 90 top
D4CB15  0.1UF/6.3V  [MX_C0201]  209.93 109.86 180 top
D4CB16  0.1UF/6.3V  [MX_C0201]  212.52 111.61 270 top
D4CB17  1UF/6.3V  [MX_C0402_SMALL_T01]  211.46 160.78 270 top
D4CB18  1UF/6.3V  [MX_C0402_SMALL_T01]  207.52 180.21 0 top
D4CB19  1UF/6.3V  [MX_C0402_SMALL_T01]  172.34 185.17 135 top
D4CB20  1UF/6.3V  [MX_C0402_SMALL_T01]  190.63 154.15 90 top
D4CB21  22UF/6.3V  [MX_C0603_SMALL_T02]  190.75 156.21 90 top
D4CB22  22UF/6.3V  [MX_C0603_SMALL_T02]  190.75 168.4 270 top
D4CB23  22UF/6.3V  [MX_C0603_SMALL_T02]  209.6 167.63 270 top
D4CB24  22UF/6.3V  [MX_C0603_SMALL_T02]  208.25 168 270 top
D4CB25  0.1UF/6.3V  [MX_C0201]  208.71 160.78 270 top
D4CB26  22UF/6.3V  [MX_C0603_SMALL_T02]  166.12 181.28 135 top
D4CB27  1UF/6.3V  [MX_C0402_SMALL_T01]  173.99 174.12 180 top
D4CB28  22UF/6.3V  [MX_C0603_SMALL_T02]  167.92 160.45 270 top
D4CB29  22UF/6.3V  [MX_C0603_SMALL_T02]  190.8 174.17 270 top
D4CB30  22UF/6.3V  [MX_C0603_SMALL_T02]  210.87 164.67 90 top
D4CB31  22UF/6.3V  [MX_C0603_SMALL_T02]  169.29 160.45 270 top
D4CB32  22UF/6.3V  [MX_C0603_SMALL_T02]  209.23 172.19 90 top
D4CB33  1UF/6.3V  [MX_C0402_SMALL_T01]  208.11 172.21 90 top
D4CB34  1UF/6.3V  [MX_C0402_SMALL_T01]  158.83 173.79 135 top
D4CB35  1UF/6.3V  [MX_C0402_SMALL_T01]  209.65 164.62 90 top
D4CB36  1UF/6.3V  [MX_C0402_SMALL_T01]  210.39 172.19 90 top
D4CB37  1UF/6.3V  [MX_C0402_SMALL_T01]  164.82 179.86 135 top
D4CB38  22UF/6.3V  [MX_C0603_SMALL_T02]  207.52 176.28 0 top
D4CB39  22UF/6.3V  [MX_C0603_SMALL_T02]  207.52 174.88 0 top
D4CB40  22UF/6.3V  [MX_C0603_SMALL_T02]  163.32 178.44 135 top
D4CB41  22UF/6.3V  [MX_C0603_SMALL_T02]  207.52 177.67 0 top
D4CB48  1UF/6.3V  [MX_C0402_SMALL_T01]  131.04 152.53 180 top
D4CB49  1UF/6.3V  [MX_C0402_SMALL_T01]  207.2 172.21 90 top
D4CB50  1UF/6.3V  [MX_C0402_SMALL_T01]  190.75 197.1 270 top
D4CB51  1UF/6.3V  [MX_C0402_SMALL_T01]  170.43 160.83 270 top
D4CB52  1UF/6.3V  [MX_C0402_SMALL_T01]  190.75 214.96 270 top
D4CB53  1UF/6.3V  [MX_C0402_SMALL_T01]  190.75 206.5 270 top
D4CB54  1UF/6.3V  [MX_C0402_SMALL_T01]  190.75 170.43 270 top
D4CB55  1UF/6.3V  [MX_C0402_SMALL_T01]  190.83 178.56 270 top
D4CB57  0.1UF/6.3V  [MX_C0201]  207.8 160.78 270 top
D4CB58  0.1UF/6.3V  [MX_C0201]  190.78 187.32 270 top
D4CB59  0.1UF/6.3V  [MX_C0201]  210.54 160.78 270 top
D4CB60  0.1UF/6.3V  [MX_C0201]  190.75 146.81 270 top
D4CB61  0.1UF/6.3V  [MX_C0201]  208.79 164.59 90 top
D4CB62  0.1UF/6.3V  [MX_C0201]  190.83 180.54 270 top
D4CB63  22UF/6.3V  [MX_C0603_SMALL_T02]  161.52 176.45 135 top
D4CB64  0.1UF/6.3V  [MX_C0201]  170.61 181.48 0 top
D4CB65  0.1UF/6.3V  [MX_C0201]  209.63 160.78 270 top
D4CB66  1UF/6.3V  [MX_C0402_SMALL_T01]  173.99 181.48 180 top
D4CB67  1UF/6.3V  [MX_C0402_SMALL_T01]  173.18 154.53 180 top
D4CB68  1UF/6.3V  [MX_C0402_SMALL_T01]  167.59 182.4 135 top
D4CB69  0.1UF/6.3V  [MX_C0201]  207.16 168.35 270 top
D4CB70  0.1UF/6.3V  [MX_C0201]  190.75 148.84 90 top
D4CB71  22UF/6.3V  [MX_C0603_SMALL_T02]  160.15 175.08 135 top
D4CB72  0.1UF/6.3V  [MX_C0201]  190.78 131.57 270 top
D4CB73  0.1UF/6.3V  [MX_C0201]  190.75 141.99 90 top
D4CB74  0.1UF/6.3V  [MX_C0201]  190.75 176.33 270 top
D4CB75  0.1UF/6.3V  [MX_C0201]  207.52 173.76 0 top
D4CB76  0.1UF/6.3V  [MX_C0201]  190.75 224.51 270 top
D4CB77  0.1UF/6.3V  [MX_C0201]  190.73 150.7 270 top
D4CB78  0.1UF/6.3V  [MX_C0201]  173.99 169.16 180 top
D4CB86  0.022UF/16V  [MX_C0402_SMALL_T01]  208.53 234.19 90 top
D4CB87  0.022UF/16V  [MX_C0402_SMALL_T01]  165.61 226.57 90 top
D4CB88  22UF/6.3V  [MX_C0603_SMALL_T02]  130.71 156.06 180 top
D4CB89  22UF/6.3V  [MX_C0603_SMALL_T02]  130.71 154.69 180 top
D4CE4  820UF/2.5V  [MX_CE_98_BD268_H374_37_LFH]  168.28 167.89 0 top
D4R1  240  [MX_R0402_SMALL_T01]  190.75 158.29 90 top
D4R3  0  [MX_R0402_SMALL_T01]  207.28 182.51 180 top
D4R10  240  [MX_R0402_SMALL_T01]  190.75 160.02 270 top
D4R15  240  [MX_R0402_SMALL_T01]  190.75 161.93 270 top
D4R20  1K  [MX_R0402_SMALL_T01]  208.15 230.53 0 top
D4R21  1K  [MX_R0402_SMALL_T01]  206.88 232.66 90 top
D4R24  240  [MX_R0402_SMALL_T01]  206.88 160.35 270 top
D4R30  2  [MX_R0402_SMALL_T01]  208.15 231.44 180 top
D4R31  24.9  [MX_R0402_SMALL_T01]  207.26 234.57 0 top
D4R32  1K  [MX_R0402_SMALL_T01]  167.64 226.57 270 top
D4R33  1K  [MX_R0402_SMALL_T01]  171.2 229.16 270 top
D4R34  2  [MX_R0402_SMALL_T01]  166.62 226.57 90 top
D4R35  24.9  [MX_R0402_SMALL_T01]  164.59 226.57 90 top
D20  BAT54CW  [MX_SOT323]  133.45 63.93 0 top
E16  HEADER_2X6P_K6  [MX_HD_2X6P_79_K6_PINRE_LF5]  182.25 5.59 180 top
EC22  0.1UF/6.3V  [MX_C0201]  230.25 171.58 90 top
ECC55  1UF/6.3V  [MX_C0402_SMALL_T01]  132.72 96.01 90 top
ECC56  0.1UF/16V  [MX_C0402_SMALL_T01]  129.36 92.48 270 top
ECQ12  PMBS3904  [MX_SOT23]  126.75 93.09 0 top
ECQ13  PMBS3904  [MX_SOT23]  132.89 93.57 0 top
ECR67  0  [MX_R0402_SMALL_T01]  204.93 24.08 0 top
ECR90  10K  [MX_R0402_SMALL_T01]  123.95 93.98 270 top
ECR92  1K  [MX_R0402_SMALL_T01]  131.8 96.01 270 top
ECR96  0  [MX_R0402_SMALL_T01]  222.47 43.31 90 top
ECR97  0  [MX_R0402_SMALL_T01]  204.17 25.04 0 top
ECR98  0  [MX_R0402_SMALL_T01]  225.54 35.2 180 top
ECR101  0  [MX_R0402_SMALL_T01]  218.29 19.51 180 top
ECR103  0  [MX_R0402_SHORT_SMALL_T01]  210.06 22.05 90 top
ECR104  0  [MX_R0402_SMALL_T01]  225.91 25.29 0 top
ECR105  10K  [MX_R0402_SMALL_T01]  130.28 92.48 90 top
F3CB1  68PF/50V  [MX_C0402_SMALL_T01]  185.98 8.85 180 top
F3CB3  0.1UF/16V  [MX_C0402_SMALL_T01]  178.3 10.97 270 top
F3CB4  0.1UF/6.3V  [MX_C0201]  177.42 11.05 270 top
F3R3  1K  [MX_R0402_SMALL_T01]  176.91 8.66 0 top
F3R4  0  [MX_R0402_SMALL_T01]  187.3 9.27 270 top
F3R6  1K  [MX_R0402_SMALL_T01]  176.28 12.95 270 top
F3R7  0  [MX_R0402_SHORT_SMALL_T01]  183.85 22.1 90 top
F3R8  0  [MX_R0402_SHORT_SMALL_T01]  187.78 21.15 270 top
F3R10  1K  [MX_R0402_SMALL_T01]  181.46 9.27 90 top
F3R12  1.5K  [MX_R0402_SMALL_T01]  174.75 4.85 0 top
F3R13  1.5K  [MX_R0402_SMALL_T01]  183.3 9.27 90 top
F3R14  0  [MX_R0402_SHORT_SMALL_T01]  186.82 23.24 270 top
F3R20  0  [MX_R0402_SHORT_SMALL_T01]  185.85 23.24 270 top
F3R21  0  [MX_R0402_SHORT_SMALL_T01]  182.65 22.1 270 top
F3U1  W25Q128FVSIQ  [MX_SOIC_8P_50_213X311]  182.1 14.92 90 top
F3U2  MX25L512EMI-10G  [MX_SOIC_8P_50_197X236]  39.62 186.18 0 top
FC2  0.1UF/16V  [MX_C0402_SMALL_T01]  130.33 233.5 90 top
FC3  0.1UF/16V  [MX_C0402_SMALL_T01]  135.64 234.44 90 top
FC5  0.1UF/16V  [MX_C0402_SMALL_T01]  234.11 225.73 270 top
FC6  0.1UF/16V  [MX_C0402_SMALL_T01]  232.56 226.67 0 top
FC8  0.1UF/16V  [MX_C0402_SMALL_T01]  192.02 50.03 0 top
FC13  10UF/16V  [MX_C0805_SMALL_T02]  18.62 153.59 180 top
FC14  10PF/50V  [MX_C0402_SMALL_T01]  234.57 218.11 270 top
FC15  10PF/50V  [MX_C0402_SMALL_T01]  139.22 238.58 270 top
FC16  10PF/50V  [MX_C0402_SMALL_T01]  114.78 237.87 270 top
FCE1  22UF/16V  [MX_C1206_H75]  112.83 237.13 90 top
FCE4  22UF/16V  [MX_C1206_H75]  143.54 237.72 90 top
FCE5  22UF/16V  [MX_C1206_H75]  232.54 221.06 270 top
FD1  BAT54CW  [MX_SOT323]  128.14 234.06 0 top
FD3  BAT54AW  [MX_SOT323]  124.71 234.06 0 top
FD7  BAT54AW  [MX_SOT323]  145.34 232.82 0 top
FD8  BAT54CW  [MX_SOT323]  232.15 228.76 270 top
FD9  BAT54AW  [MX_SOT323]  231.69 224.99 0 top
FD10  BAT54CW  [MX_SOT323]  151.64 234.01 180 top
FR1  8.2K  [MX_R0402_SMALL_T01]  136.65 234.44 90 top
FR2  150  [MX_R0805_SMALL_T02]  134.11 233.83 90 top
FR8  8.2K  [MX_R0402_SMALL_T01]  136.65 232.79 270 top
FR17  0  [MX_R0402_SMALL_T01]  135.64 232.79 270 top
FR28  150  [MX_R0805_SMALL_T02]  234.26 228.02 90 top
FR29  0  [MX_R0402_SMALL_T01]  230.94 226.67 180 top
FR30  8.2K  [MX_R0402_SMALL_T01]  234.31 229.92 0 top
FR31  8.2K  [MX_R0402_SMALL_T01]  230.43 228.35 270 top
FR32  150  [MX_R0805_SMALL_T02]  148.46 234.31 0 top
FR33  8.2K  [MX_R0402_SMALL_T01]  144.27 234.49 0 top
FR35  8.2K  [MX_R0402_SMALL_T01]  143.26 233.22 270 top
FR36  33  [MX_R0402_SMALL_T01]  130.71 234.85 0 top
FR37  33  [MX_R0402_SMALL_T01]  91.83 12.69 270 top
GFX_Q1  PMBS3904  [MX_SOT23]  66.85 73.84 270 top
GPU_PWR  POWER_CON_8P  [MX_PWR_8P_165_2HOLD_VIT_LF3]  62.61 103.12 180 top
H1  SCREWHOLE_160_HP  [MX_HOLE_160_T_U_HP]  33.02 237.49 0 top
H2  SCREWHOLE_160_HP  [MX_HOLE_160_T_R_HP]  237.49 80.01 0 top
H3  SCREWHOLE_160_HP  [MX_HOLE_160_T_U_HP]  165.1 237.49 0 top
H4  SCREWHOLE_160_HP  [MX_HOLE_160_T_HP]  165.1 80.01 0 top
H5  SCREWHOLE_160_HP  [MX_HOLE_160_T_HP]  165.1 13.97 0 top
H6  C315D189N  [MX_H_C315D189N_M2_P2_V8]  237.49 237.49 0 top
H7  C315D189N  [MX_HOLE_C315D189N_M2_P2_V8]  10.16 34.29 0 top
H8  C315D189N  [MX_HOLE_C315D189N_M2_P2_V8]  10.16 80.01 0 top
H13  CT276B195D165  [MX_SMT_NUT_CT276B195D165]  36.67 89.98 180 top
H14  CT299B196D166  [MX_SMT_N_CT299B196D166_H100]  218.36 73.38 180 top
H15  CT299B196D166  [MX_SMT_N_CT299B196D166_H100]  218.36 93.38 180 top
H16  CT299B196D166  [MX_SMT_N_CT299B196D166_H100]  218.36 55.38 0 top
H20  HT-G5025M20TCU-1  [MX_NUT_CT256BD146_H71]  95.6 221.78 0 top
H21  HT-G5025M20TCU-1  [MX_NUT_CT256BD146_H71]  59.92 210.86 0 top
H22  HT-G5025M20TCU-1  [MX_NUT_CT256BD146_H71]  148.8 221.78 0 top
H23  HT-G5025M20TCU-1  [MX_NUT_CT256BD146_H71]  59.92 132.06 0 top
HC3  22UF/6.3V  [MX_C0603_SMALL_T02]  131.17 116.56 90 top
HC4  1UF/6.3V  [MX_C0402_SMALL_T01]  128.73 117.15 90 top
HC5  0.1UF/16V  [MX_C0402_SMALL_T01]  101.73 121.79 270 top
HC11  47PF/50V  [MX_C0402_SMALL_T01]  177.44 28.47 90 top
HC23  1UF/6.3V  [MX_C0402_SMALL_T01]  101.93 118.01 90 top
HC24  47PF/50V  [MX_C0402_SMALL_T01]  93.27 206.41 90 top
HC25  0.1UF/16V  [MX_C0402_SMALL_T01]  132.59 112.93 90 top
HC27  1UF/6.3V  [MX_C0402_SMALL_T01]  129.77 152.04 90 top
HC29  0.1UF/16V  [MX_C0402_SMALL_T01]  206.15 53.75 180 top
HC30  0.1UF/16V  [MX_C0402_SMALL_T01]  13.28 72.19 270 top
HC31  0.1UF/16V  [MX_C0402_SMALL_T01]  6.12 41.78 90 top
HR4  24.9  [MX_R0402_SMALL_T01]  119.86 152.58 180 top
HR6  24.9  [MX_R0402_SMALL_T01]  119.86 151.66 180 top
HR9  100  [MX_R0402_SMALL_T01]  99.01 138.96 90 top
HR11  51  [MX_R0402_SMALL_T01]  98.42 141.73 0 top
HR14  51  [MX_R0402_SMALL_T01]  98.44 144.98 180 top
HR15  51  [MX_R0402_SMALL_T01]  98.44 144.07 180 top
HR17  0  [MX_R0402_SHORT_SMALL_T01]  89.51 208.46 90 top
HR18  0  [MX_R0402_SHORT_SMALL_T01]  91.44 206.43 270 top
HR20  220  [MX_R0402_SMALL_T01]  90.53 206.43 270 top
HR22  13  [MX_R0402_T01]  101.59 124.24 90 top
HR23  1K  [MX_R0402_SMALL_T01]  100.46 121.92 90 top
HR24  1K  [MX_R0402_SMALL_T01]  92.46 208.46 270 top
HR25  200  [MX_R0402_SMALL_T01]  100.53 119.74 315 top
HR26  499  [MX_R0402_SMALL_T01]  92.35 206.43 270 top
HR27  20  [MX_R0402_SMALL_T01]  102.74 121.79 90 top
HR28  30  [MX_R0402_SMALL_T01]  153.09 43.51 0 top
HR29  1K  [MX_R0402_SMALL_T01]  103.12 117.98 90 top
HR31  49.9  [MX_R0402_SMALL_T01]  119.86 153.52 0 top
HR32  100  [MX_R0402_SMALL_T01]  91.54 208.46 270 top
HR33  56  [MX_R0402_SMALL_T01]  90.53 208.46 270 top
HR36  1K  [MX_R0402_SMALL_T01]  94.96 118.72 135 top
HR70  0  [MX_R0402_SHORT_SMALL_T01]  131.04 151.64 0 top
HR78  20  [MX_R0402_SMALL_T01]  103.68 121.79 270 top
HR86  0  [MX_R0402_SMALL_T01]  101.96 115.75 270 top
HR615  1K  [MX_R0402_SMALL_T01]  95.63 119.38 135 top
HR616  1K  [MX_R0402_SMALL_T01]  96.33 120.6 90 top
HR617  1K  [MX_R0402_SMALL_T01]  97.24 120.6 90 top
HR618  1K  [MX_R0402_SMALL_T01]  98.3 119.13 90 top
HR619  1K  [MX_R0402_SMALL_T01]  103.09 115.77 270 top
HR620  1K  [MX_R0402_SMALL_T01]  101.04 116.43 270 top
HR621  1K  [MX_R0402_SMALL_T01]  100.13 117.63 270 top
HR622  1K  [MX_R0402_SMALL_T01]  99.21 118.19 90 top
HR626  1K  [MX_R0402_SMALL_T01]  99.69 108.71 45 top
HR627  1K  [MX_R0402_SMALL_T01]  188.72 44.07 0 top
HR629  1K  [MX_R0402_SMALL_T01]  188.06 46.66 270 top
HR630  56  [MX_R0402_SMALL_T01]  120.85 119.94 180 top
HR631  0  [MX_R0402_SMALL_T01]  136.93 210.54 90 top
HT34  TPC26T  [MX_TPC26T_S4_68]  134.62 208.13 180 bottom
HT45  TPC26T  [MX_TPC26T_S4_68]  76.07 112.14 180 bottom
HT46  TPC26T  [MX_TPC26T_S4_68]  78.79 112.42 180 bottom
HT47  TPC26T  [MX_TPC26T_S4_68]  77.65 110.9 180 bottom
HT48  TPC26T  [MX_TPC26T_S4_68]  76.15 109.88 180 bottom
HT49  TPC26T  [MX_TPC26T_S4_68]  78.11 108.2 180 bottom
HT50  TPC26T  [MX_TPC26T_S4_68]  74.37 109.55 180 bottom
HT51  TPC26T  [MX_TPC26T_S4_68]  73.4 111.48 180 bottom
HT56  TPC26T  [MX_TPC26T_S4_68]  116.93 149.08 180 bottom
J9  JACK_USB_22P  [MX_JACK_USB_22P_8H_UD_LF5]  15.02 205.23 270 top
J10  USB_CON_16P  [MX_USB_4X4P_6HD_RA_FOX_LF5]  9.28 185.15 270 top
J60  MINI_PCI_67P  [MX_MINI_PCI_67P_4HD_COLAY]  36.67 118.16 0 top
J83  AUDIO_6IN1_AZA_26P  [MX_PHONE_JACK_26P_4H_LO_LF5]  3.36 103.05 270 top
J125  DISPLAYPORT_CON_20P  [MX_DISPLY20P_39_4HLD_LF3]  8.82 164.72 270 top
J133  USB_CON_36P  [MX_USBX4_CON_36P_6HD_RA_LF5]  8.64 129.15 270 top
J_TYPEC  USB_CON_2x12P  [A_USB_CON_2X12P_8HOLD_ACON]  5.65 146.43 270 top
L1  220Ohm/100Mhz/0.6A  [MX_L0603_SMALL_T02]  40.51 210.44 90 top
L2  220Ohm/100Mhz/0.6A  [MX_L0603_SMALL_T02]  34.42 224.16 90 top
LC4  15PF/50V  [MX_C0402_SMALL_T01]  31.83 222.63 0 top
LC5  15PF/50V  [MX_C0402_SMALL_T01]  29.95 222.63 180 top
LC6  470PF/50V  [MX_C0402_SMALL_T01]  31.06 206.76 0 top
LC7  470PF/50V  [MX_C0402_SMALL_T01]  41.91 219.76 90 top
LC8  470PF/50V  [MX_C0402_SMALL_T01]  25.91 220.09 90 top
LC9  0.1UF/16V  [MX_C0402_SMALL_T01]  37.01 210.64 90 top
LC10  0.1UF/16V  [MX_C0402_SMALL_T01]  36.09 210.64 90 top
LC12  0.1UF/16V  [MX_C0402_SMALL_T01]  28.09 206.98 0 top
LC18  100PF/50V  [MX_C0402_SMALL_T01]  38.23 220.47 90 top
LC44  27PF/50V  [MX_C0402_SMALL_T01]  24.89 220.09 90 top
LC47  0.1UF/16V  [MX_C0402_SMALL_T01]  40.26 215.14 180 top
LC48  0.1UF/16V  [MX_C0402_SMALL_T01]  40.26 216.05 180 top
LCB2  1UF/6.3V  [MX_C0402_SMALL_T01]  39.98 222.25 0 top
LCB3  10UF/6.3V  [MX_C0603_SMALL_T01]  40.26 224.66 0 top
LCB4  0.1UF/6.3V  [MX_C0201]  31.06 215.52 180 top
LCB5  1UF/6.3V  [MX_C0402_SMALL_T01]  39.98 221.31 0 top
LCB6  0.1UF/6.3V  [MX_C0201]  38.48 211.73 0 top
LCB7  0.1UF/6.3V  [MX_C0201]  34.9 220.47 90 top
LCB9  0.1UF/6.3V  [MX_C0201]  38.48 210.82 0 top
LCB10  0.1UF/6.3V  [MX_C0201]  40.69 214.17 0 top
LCB11  1UF/6.3V  [MX_C0402_SMALL_T01]  30.1 220.6 180 top
LCB12  0.1UF/6.3V  [MX_C0201]  33.4 210.19 180 top
LCB13  4.7UF/6.3V  [MX_C0603_SMALL_T01]  40.51 212.17 0 top
LCB14  0.1UF/6.3V  [MX_C0201]  30.73 213.23 180 top
LCB15  1UF/6.3V  [MX_C0402_SMALL_T01]  30.15 216.99 180 top
LCB16  10UF/6.3V  [MX_C0603_SMALL_T01]  40.26 223.39 0 top
LCB17  0.1UF/6.3V  [MX_C0201]  39.98 220.37 0 top
LCB18  1000PF/50V  [MX_C0402_SMALL_T01]  39.98 219.46 0 top
LCB19  1UF/6.3V  [MX_C0402_SMALL_T01]  40.69 213.23 0 top
LCB20  0.1UF/6.3V  [MX_C0201]  33.4 211.2 180 top
LCB21  0.1UF/6.3V  [MX_C0201]  39.52 217.45 90 top
LCB22  1UF/6.3V  [MX_C0402_SMALL_T01]  40.94 217.55 90 top
LR1  4.7K  [MX_R0402_SMALL_T01]  38.23 223.37 270 top
LR2  4.7K  [MX_R0402_SMALL_T01]  35.74 223.38 90 top
LR3  510  [MX_R0402_SMALL_T01]  27.18 220.09 90 top
LR4  220  [MX_R0603_SMALL_T01]  30.53 205.54 180 top
LR5  220  [MX_R0603_SMALL_T01]  33.73 205.99 270 top
LR6  0  [MX_R0402_SMALL_T01]  37.21 220.47 270 top
LR9  10K  [MX_R0402_SMALL_T01]  42.85 219.76 90 top
LR10  220  [MX_R0402_SMALL_T01]  34.92 210.57 270 top
LR20  0  [MX_R0402_SHORT_SMALL_T01]  23.88 220.09 90 top
LR22  0  [MX_R0402_SMALL_T01]  30.05 221.69 180 top
LR23  30K  [MX_R0402_SMALL_T01]  35.74 220.47 90 top
LR24  2.37K  [MX_R0402_SMALL_T01]  30.1 219.07 180 top
M1C1  0.1UF/6.3V  [MX_C0201]  13.03 175.44 90 top
M1C12  0.1UF/16V  [MX_C0402_SMALL_T01]  35.56 175.16 180 top
M1C13  0.1UF/16V  [MX_C0402_SMALL_T01]  35.56 174.24 180 top
M1C35  0.1UF/6.3V  [MX_C0201]  19.56 169.93 0 top
M1D1  AZ5125-01J  [MX_S0402_AMAZ_COLAY]  16.76 170.43 180 top
M1F1  1.1A/6V  [MX_POLYSWITCH_2P_0805_H30]  17.61 175.84 180 top
M1R4  10K  [MX_R0402_SMALL_T01]  38.96 178.69 0 top
M1R5  10K  [MX_R0402_SMALL_T01]  36.58 177.16 270 top
M1R8  100K  [MX_R0402_SMALL_T01]  30.76 176.53 90 top
M1R11  100K  [MX_R0402_SMALL_T01]  28.96 173.99 90 top
M1R12  2.2K  [MX_R0402_SMALL_T01]  23.06 174.6 0 top
M1R13  2.2K  [MX_R0402_SMALL_T01]  23.06 173.46 0 top
M1R36  1M  [MX_R0402_SMALL_T01]  19.56 170.84 0 top
M1R37  1M  [MX_R0402_SMALL_T01]  14.82 170.25 0 top
M1R40  100K  [MX_R0402_SMALL_T01]  136.02 96.01 270 top
M1U1  IP4284CZ10-TB  [MX_ESD_10P_20_98X39_NXP]  15.77 164.06 90 top
M1U2  IP4284CZ10-TB  [MX_ESD_10P_20_98X39_NXP]  15.77 167.67 90 top
M1U3  IP4284CZ10-TB  [MX_ESD_10P_20_98X39_NXP]  28.22 196.27 270 top
M1U4  IP4284CZ10-TB  [MX_ESD_10P_20_98X39_NXP]  25.05 181.54 270 top
M1U5  IP4284CZ10-TB  [MX_ESD_10P_20_98X39_NXP]  25.06 184.82 270 top
M1U6  IP4284CZ10-TB  [MX_ESD_10P_20_98X39_NXP]  11.23 119.08 90 top
M1U7  IP4284CZ10-TB  [MX_ESD_10P_20_98X39_NXP]  18.59 119.38 180 top
M1U8  IP4284CZ10-TB  [MX_ESD_10P_20_98X39_NXP]  25.7 216.08 0 top
M1U9  IP4284CZ10-TB  [MX_ESD_10P_20_98X39_NXP]  28.3 211.73 270 top
M2C1  22UF/6.3V  [MX_C0603_SMALL_T02]  50.86 115.72 270 top
M2C2  0.1UF/16V  [MX_C0402_SMALL_T01]  24.91 116.79 90 top
M2C3  0.01UF/50V  [MX_C0402_SMALL_T01]  23.08 116.79 90 top
M2C4  22UF/6.3V  [MX_C0603_SMALL_T02]  22 105.94 180 top
M2C5  0.1UF/16V  [MX_C0402_SMALL_T01]  48.82 116.79 90 top
M2C6  0.01UF/50V  [MX_C0402_SMALL_T01]  24 116.79 90 top
M2C13  22UF/6.3V  [MX_C0603_SMALL_T02]  203.38 15.95 180 top
M2C14  0.1UF/16V  [MX_C0402_SMALL_T01]  223.93 19.92 90 top
M2C15  0.01UF/50V  [MX_C0402_SMALL_T01]  224.84 19.92 90 top
M2C16  22UF/6.3V  [MX_C0603_SMALL_T02]  203.38 14.61 180 top
M2C17  0.1UF/16V  [MX_C0402_SMALL_T01]  226.61 19.91 90 top
M2C18  0.01UF/50V  [MX_C0402_SMALL_T01]  227.53 19.91 90 top
M2C19  22UF/6.3V  [MX_C0603_SMALL_T02]  222.35 19.76 180 top
M2C20  0.1UF/16V  [MX_C0402_SMALL_T01]  205.97 17.6 90 top
M2C21  0.01UF/50V  [MX_C0402_SMALL_T01]  203.56 17.17 180 top
M2C22  0.22UF/10V  [MX_C0402_SMALL_T01]  216.34 8.62 270 top
M2C23  0.22UF/10V  [MX_C0402_SMALL_T01]  215.43 8.62 270 top
M2C24  0.22UF/10V  [MX_C0402_SMALL_T01]  218.41 8.65 270 top
M2C25  0.22UF/10V  [MX_C0402_SMALL_T01]  219.33 8.65 270 top
M2C26  0.22UF/10V  [MX_C0402_SMALL_T01]  221.39 8.65 270 top
M2C27  0.22UF/10V  [MX_C0402_SMALL_T01]  222.3 8.65 270 top
M2C28  0.22UF/10V  [MX_C0402_SMALL_T01]  224.44 8.65 270 top
M2C29  0.22UF/10V  [MX_C0402_SMALL_T01]  225.36 8.65 270 top
M2C40  0.22UF/10V  [MX_C0402_SMALL_T01]  49.25 122.48 0 top
M2C41  0.22UF/10V  [MX_C0402_SMALL_T01]  49.25 123.47 0 top
M2C44  100PF/50V  [MX_C0402_SMALL_T01]  212.37 8.26 270 top
M2C46  0.1UF/16V  [MX_C0402_SMALL_T01]  51 117.78 0 top
M2C47  0.1UF/16V  [MX_C0402_SMALL_T01]  51 118.95 0 top
M2C48  100PF/50V  [MX_C0402_SMALL_T01]  53.26 118.64 180 top
M2C49  10PF/50V  [MX_C0402_SMALL_T01]  49.73 116.79 90 top
M2C50  10PF/50V  [MX_C0402_SMALL_T01]  22.3 107.16 180 top
M2C51  10PF/50V  [MX_C0402_SMALL_T01]  204.98 17.6 90 top
M2C52  10PF/50V  [MX_C0402_SMALL_T01]  206.22 14 270 top
M2C53  10PF/50V  [MX_C0402_SMALL_T01]  49.25 121.03 0 top
M2C54  10PF/50V  [MX_C0402_SMALL_T01]  209.6 8.26 270 top
M2C55  10PF/50V  [MX_C0402_SMALL_T01]  205.21 14.02 270 top
M2R1  10K  [MX_R0402_SMALL_T01]  207.77 8.26 90 top
M2R4  0  [MX_R0402_SMALL_T01]  43.94 125.98 90 top
M2R33  0  [MX_R0402_SMALL_T01]  208.69 8.26 90 top
M2R34  0  [MX_R0402_SMALL_T01]  210.52 8.26 90 top
M2R36  0  [MX_R0402_SMALL_T01]  211.46 8.26 90 top
M2R39  0  [MX_R0402_SMALL_T01]  32.18 125.83 0 top
M2R40  0  [MX_R0402_SHORT_SMALL_T01]  63.17 75.16 90 top
M2R41  0  [MX_R0402_SHORT_SMALL_T01]  63.75 54.86 90 top
M2R43  0  [MX_R0402_SHORT_SMALL_T01]  63.45 34.65 90 top
M2R44  0  [MX_R0402_SHORT_SMALL_T01]  62.26 15.88 0 top
M2R45  0  [MX_R0402_SHORT_SMALL_T01]  225.73 19.91 270 top
M2R46  0  [MX_R0402_SMALL_T01]  49.25 119 180 top
M2R47  0  [MX_R0402_SMALL_T01]  49.25 118.08 180 top
M2R52  0  [MX_R0402_SMALL_T01]  23.04 154.05 180 top
M2R54  0  [MX_R0402_SMALL_T01]  43.05 125.98 90 top
MQ4  SSM3K315T  [MX_SOT23_2D4_H44]  23.19 167.92 90 top
MQ8  UM6K1N  [MX_SOT363]  39.12 176.78 270 top
MQ10  UM6K1N  [MX_SOT363]  33.02 175.13 180 top
MQ12  UM6K1N  [MX_SOT363]  26.29 174.75 270 top
MQ15  2N7002  [MX_SOT23_H43]  15.72 172.92 0 top
MQ18  2N7002  [MX_SOT23_H43]  36.58 205.74 0 top
MQ19  UM6K1N  [MX_SOT363]  228.06 80.69 180 top
MQ20  UM6K1N  [MX_SOT363]  222 108.18 180 top
MQ21  UM6K1N  [MX_SOT363]  130.51 110.66 270 top
MQ22  2N7002  [MX_SOT23_H43]  22.1 230.02 0 top
MQ23  PMV33UPE  [MX_SOT23_2D4_H43]  20.32 233.53 270 top
MQ24  UM6K1N  [MX_SOT363]  209.3 215.65 0 top
MQ25  UM6K1N  [MX_SOT363]  228.5 153.62 0 top
MQ26  UM6K1N  [MX_SOT363]  227.33 199.9 0 top
MQ28  UM6K1N  [MX_SOT363]  205.99 48.39 0 top
MQ29  UM6K1N  [MX_SOT363]  137.79 94.36 0 top
MQ35  UM6K1N  [MX_SOT363]  210.94 50.78 270 top
MR41  100K  [MX_R0402_SMALL_T01]  13.08 171.96 90 top
NOREF  -  []  178.57 239.51 0 top
NOREF#2  -  []  195.58 2.36 0 top
NOREF#3  -  []  133.38 43.79 0 top
NOREF#4  -  []  85.03 42.99 0 top
NOREF#5  -  []  38.05 17.6 0 top
NOREF#6  -  []  182.25 1.93 0 top
NOREF#7  -  []  203.01 239.47 0 top
NOREF#8  -  []  85.31 88.81 0 top
NOREF#9  -  []  13.92 159.74 90 top
NOREF#10  -  []  100.37 61.84 0 top
NOREF#11  -  []  38 36.6 0 top
NOREF#12  -  []  241.22 28.09 90 top
NOREF#13  -  []  115.15 88.81 0 top
NOREF#14  -  []  186.83 239.55 0 top
NOREF#15  -  []  25.16 188.89 90 top
NOREF#16  -  []  83.74 34.52 0 top
NOREF#17  -  []  238.86 140.3 0 top
NOREF#18  -  []  96.01 88.8 0 top
NOREF#19  -  []  152.04 69.29 90 top
NOREF#20  -  []  241.2 63.19 90 top
NOREF#21  -  []  223.11 6.02 0 top
NOREF#22  -  []  109.75 2.13 0 top
NOREF#23  -  []  154.38 230.3 90 top
NOREF#24  -  []  99.33 45.9 0 top
